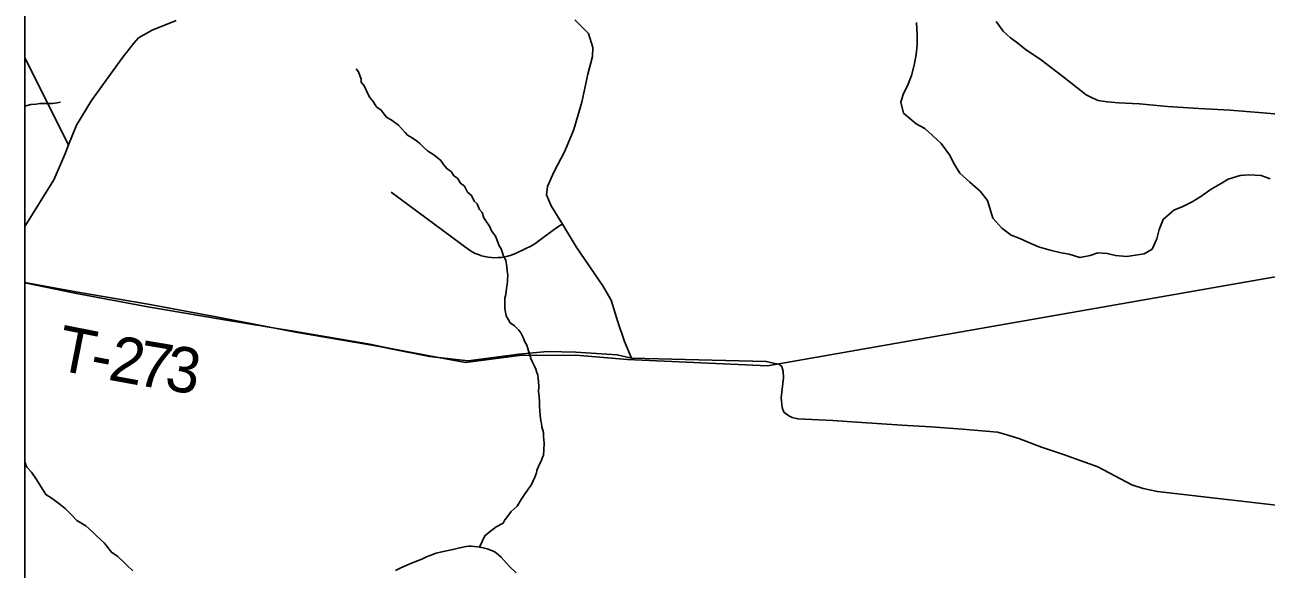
# Model space of a CAD drawing. Extents: x 0 to 39.3, y -3.9 to 22.
# Drawn here: x 1.9 to 3.453, y 15.491 to 16.173 of the extents above; entities that cross this region are included whole.
import ezdxf

# ---------------------------------------------------------------- set-up
doc = ezdxf.new("R2010")
doc.units = 0
for name, color, linetype in [('GM_X_Corporation', 7, 'Continuous'), ('GM_X_Minor_River', 7, 'Continuous'), ('GM_X_State_Route', 7, 'Continuous'), ('GM_X_Township_Road', 7, 'Continuous'), ('GM_X_Township_Road_Text', 7, 'Continuous'), ('SH_Data', 7, 'Continuous')]:
    doc.layers.add(name, color=color, linetype=linetype)

msp = doc.modelspace()

# ---------------------------------------------------------------- linework, layer by layer
at = {"layer": 'GM_X_Corporation'}
for points in [[(1.9, 20.2403), (1.9, 15.8496), (1.9627, 15.8365), (2.054, 15.8197), (2.1447, 15.8042), (2.2384, 15.7885), (2.3314, 15.7727), (2.3534, 15.7684), (2.406, 15.7581), (2.4514, 15.75), (2.5183, 15.7585), (2.5893, 15.7591), (2.6537, 15.7535), (2.8288, 15.7458), (2.8431, 15.7483), (3.5402, 15.8703)], [(3.5402, 15.8703), (2.8431, 15.7483), (2.8288, 15.7458), (2.6537, 15.7535), (2.5893, 15.7591), (2.5183, 15.7585), (2.4514, 15.75), (2.406, 15.7581), (2.3534, 15.7684), (2.3314, 15.7727), (2.2384, 15.7885), (2.1447, 15.8042), (2.054, 15.8197), (1.9627, 15.8365), (1.9, 15.8496), (1.9, 13.9), (3.8692, 13.9)]]:
    msp.add_lwpolyline(points, dxfattribs=at)
at = {"layer": 'GM_X_Minor_River'}
for points in [[(3.0153, 16.1754), (3.0162, 16.1601), (3.016, 16.1472), (3.015, 16.1354), (3.0125, 16.1222), (3.0092, 16.1089), (3.0049, 16.0984), (2.9986, 16.0855), (2.9958, 16.0757), (2.9989, 16.062), (3.015, 16.0488), (3.0256, 16.0429), (3.0353, 16.034), (3.0461, 16.0239), (3.0565, 16.01), (3.0627, 15.9977), (3.0694, 15.987), (3.0821, 15.9757), (3.0948, 15.9645), (3.1041, 15.9525), (3.107, 15.943), (3.1109, 15.9307), (3.1221, 15.918), (3.1337, 15.9094), (3.1447, 15.905), (3.1545, 15.9007), (3.168, 15.8947), (3.1824, 15.8903), (3.1964, 15.887), (3.2062, 15.8853), (3.2198, 15.8813), (3.2327, 15.8837), (3.2423, 15.887), (3.254, 15.8864), (3.2643, 15.8839), (3.2783, 15.8825), (3.2893, 15.8842), (3.3, 15.886), (3.3103, 15.8919), (3.3162, 15.9047), (3.3191, 15.9164), (3.3239, 15.9289), (3.3373, 15.9404), (3.3484, 15.9452), (3.3603, 15.9511), (3.371, 15.9577), (3.3841, 15.967), (3.3956, 15.9733), (3.4052, 15.9792), (3.4201, 15.9838), (3.4311, 15.9848), (3.4467, 15.9841), (3.4576, 15.9798)], [(2.4035, 16.0146), (2.3994, 16.0185), (2.3941, 16.0239), (2.3911, 16.0266), (2.3847, 16.0309), (2.3787, 16.0344), (2.3757, 16.0379), (2.3709, 16.0433), (2.3675, 16.0468), (2.3596, 16.0527), (2.3525, 16.057), (2.3495, 16.0608), (2.3458, 16.0658), (2.3405, 16.0693), (2.3383, 16.0724), (2.3357, 16.0767), (2.3327, 16.0798), (2.3309, 16.0828), (2.3272, 16.0901), (2.3246, 16.0963), (2.3209, 16.1009), (2.3206, 16.1043), (2.3173, 16.1135), (2.3144, 16.1174)], [(1.9, 16.0709), (1.9075, 16.0727), (1.914, 16.0733), (1.9189, 16.074), (1.9261, 16.0742), (1.9345, 16.074), (1.9406, 16.075), (1.9447, 16.0758)], [(2.4687, 15.5187), (2.4755, 15.533), (2.4805, 15.5371), (2.4897, 15.5441), (2.4982, 15.549), (2.4998, 15.5523), (2.5084, 15.5636), (2.5157, 15.57), (2.5208, 15.5783), (2.524, 15.5835), (2.5298, 15.5914), (2.5333, 15.5963), (2.5353, 15.6008), (2.5381, 15.6065), (2.5401, 15.6118), (2.5405, 15.6148), (2.5433, 15.622), (2.5457, 15.6266), (2.5473, 15.63), (2.5489, 15.6341), (2.5493, 15.6402), (2.5495, 15.6493), (2.5489, 15.6569), (2.5486, 15.6623), (2.5468, 15.6695), (2.5461, 15.6737), (2.5454, 15.6768), (2.5451, 15.6806), (2.5448, 15.6837), (2.5441, 15.6894), (2.5439, 15.6947), (2.5436, 15.7004), (2.5433, 15.7073), (2.5427, 15.7138), (2.5428, 15.7199), (2.5425, 15.7263), (2.5422, 15.7298), (2.5415, 15.734), (2.5401, 15.7386), (2.539, 15.7416), (2.5376, 15.7455), (2.5357, 15.7485), (2.5346, 15.7512), (2.5331, 15.7547), (2.5321, 15.7577), (2.5314, 15.7608), (2.5299, 15.7646), (2.5292, 15.7673), (2.5281, 15.7715), (2.5255, 15.7757), (2.5237, 15.7803), (2.5204, 15.7869), (2.5178, 15.7903), (2.5126, 15.7958), (2.5073, 15.7996), (2.5051, 15.8035), (2.5021, 15.8081), (2.5004, 15.8173), (2.5006, 15.8306), (2.5015, 15.8351), (2.5019, 15.8389), (2.5024, 15.8424), (2.5032, 15.8481), (2.5037, 15.8511), (2.5037, 15.8541), (2.5042, 15.8591), (2.5035, 15.8644), (2.5029, 15.8698), (2.5015, 15.8778), (2.4989, 15.8828), (2.4975, 15.887), (2.4957, 15.892), (2.4934, 15.8958), (2.4916, 15.9004), (2.4887, 15.9081), (2.4839, 15.9146), (2.4813, 15.9204), (2.4765, 15.9273), (2.4743, 15.9308), (2.4721, 15.9377), (2.4688, 15.9415), (2.4659, 15.9484), (2.4621, 15.9519), (2.4588, 15.9588), (2.4536, 15.9631), (2.4499, 15.9704), (2.445, 15.9743), (2.4413, 15.9804), (2.4368, 15.9836), (2.4331, 15.989), (2.4282, 15.9921), (2.4237, 15.9979), (2.4204, 16.0025), (2.4118, 16.0099), (2.4035, 16.0146)], [(2.0353, 15.4892), (2.0279, 15.4958), (2.0237, 15.5001), (2.0163, 15.5071), (2.0084, 15.5125), (1.9991, 15.5241), (1.9949, 15.528), (1.9882, 15.5342), (1.9845, 15.5381), (1.9762, 15.5454), (1.9649, 15.5521), (1.9593, 15.5583), (1.9504, 15.5672), (1.9444, 15.5722), (1.9342, 15.5797), (1.9263, 15.5847), (1.923, 15.5901), (1.9178, 15.5982), (1.9148, 15.6036), (1.9085, 15.6125), (1.9026, 15.619), (1.9, 15.6254)], [(2.3637, 15.4895), (2.3703, 15.4929), (2.3806, 15.4973), (2.3856, 15.4998), (2.3967, 15.5038), (2.4025, 15.5068), (2.4147, 15.5111), (2.4216, 15.5129), (2.4354, 15.5157), (2.4419, 15.5175), (2.4522, 15.5196), (2.4552, 15.52), (2.4583, 15.5199), (2.4621, 15.5195), (2.4666, 15.519), (2.4735, 15.5181), (2.4784, 15.5165), (2.4848, 15.5141), (2.4882, 15.5125), (2.4927, 15.509), (2.4957, 15.5063), (2.5024, 15.4986), (2.5062, 15.4947), (2.5148, 15.4866)]]:
    msp.add_lwpolyline(points, dxfattribs=at)
at = {"layer": 'GM_X_State_Route'}
msp.add_lwpolyline([(3.1152, 16.1765), (3.1238, 16.1647), (3.133, 16.1562), (3.1405, 16.1506), (3.1514, 16.1419), (3.1718, 16.1281), (3.1983, 16.1079), (3.2274, 16.0849), (3.2349, 16.0813), (3.2424, 16.078), (3.2537, 16.0762), (3.2685, 16.0747), (3.2944, 16.0735), (3.3292, 16.0703), (3.3686, 16.0678), (3.4079, 16.0655), (3.4486, 16.0623), (3.4824, 16.0596)], dxfattribs=at)
at = {"layer": 'GM_X_Township_Road'}
msp.add_line((1.9548, 16.0224), (1.9, 16.1312), dxfattribs=at)
for points in [[(1.9, 15.92), (1.9363, 15.9783), (1.9501, 16.0104), (1.9548, 16.0224), (1.9647, 16.0471), (1.9832, 16.0778), (2.0071, 16.1108), (2.0228, 16.1319), (2.0362, 16.1496), (2.0422, 16.1562), (2.0593, 16.1657), (2.0893, 16.178)], [(2.5879, 16.1789), (2.6052, 16.1618), (2.6107, 16.1443), (2.6101, 16.133), (2.6044, 16.1108), (2.5966, 16.0755), (2.5867, 16.0413), (2.5753, 16.0142), (2.5617, 15.988), (2.5539, 15.9701), (2.5524, 15.9599), (2.5585, 15.9461), (2.5727, 15.9232), (2.5898, 15.8948), (2.6231, 15.8459), (2.6334, 15.8277), (2.6419, 15.8009), (2.6502, 15.7763), (2.6587, 15.7555)], [(2.3583, 15.9631), (2.4561, 15.8905), (2.4597, 15.8884), (2.4634, 15.8865), (2.4673, 15.8849), (2.4713, 15.8835), (2.4753, 15.8825), (2.4794, 15.8817), (2.4836, 15.8812), (2.4877, 15.881), (2.4919, 15.8811), (2.4961, 15.8815), (2.5002, 15.8822), (2.5042, 15.8831), (2.5082, 15.8844), (2.5136, 15.8865), (2.5258, 15.8923), (2.5328, 15.8955), (2.5378, 15.8983), (2.5447, 15.9034), (2.5592, 15.9144), (2.5694, 15.9213), (2.5727, 15.9232)], [(1.9, 15.8499), (1.9638, 15.8383), (2.0542, 15.8231), (2.146, 15.806), (2.2387, 15.7879), (2.3316, 15.7722), (2.3498, 15.7686)], [(2.3498, 15.7686), (2.3536, 15.7679), (2.4062, 15.7575), (2.4546, 15.7519), (2.5178, 15.7602), (2.5538, 15.7637), (2.5894, 15.7627), (2.6408, 15.7593), (2.6587, 15.7555), (2.8274, 15.7513), (2.8367, 15.7492)], [(2.8367, 15.7492), (2.8433, 15.7478), (2.8468, 15.7448), (2.8487, 15.7387), (2.8489, 15.7305), (2.846, 15.7056), (2.8474, 15.6937), (2.8496, 15.6878), (2.8558, 15.683), (2.8599, 15.6811), (2.8669, 15.6793), (2.9108, 15.6771), (2.9408, 15.6751), (2.9971, 15.6713), (3.0333, 15.6693), (3.0729, 15.6666), (3.1168, 15.6627), (3.1241, 15.6607), (3.1432, 15.6546), (3.1719, 15.6438), (3.1993, 15.6346), (3.2423, 15.6192), (3.2848, 15.5967), (3.2988, 15.5922), (3.3168, 15.5883), (3.5047, 15.5667)]]:
    msp.add_lwpolyline(points, dxfattribs=at)
at = {"layer": 'SH_Data'}
msp.add_lwpolyline([(1.9, 21.1), (9.1, 21.1), (9.1, 13.9), (1.9, 13.9)], close=True, dxfattribs=at)

# ---------------------------------------------------------------- texts
at = {"layer": 'GM_X_Township_Road_Text'}
for s, rotation, p in [('T', 348.9015, (1.9374, 15.7413)), ('2', 349.6405, (2.0028, 15.7286)), ('7', 350.3794, (2.038, 15.7221)), ('3', 351.1336, (2.0733, 15.7161)), ('-', 349.1067, (1.9793, 15.7331))]:
    msp.add_text(s, height=0.0568, rotation=rotation, dxfattribs=at).set_placement(p)

doc.saveas('drawing.dxf')
